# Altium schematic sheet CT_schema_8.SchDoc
size 405 x 220 mm
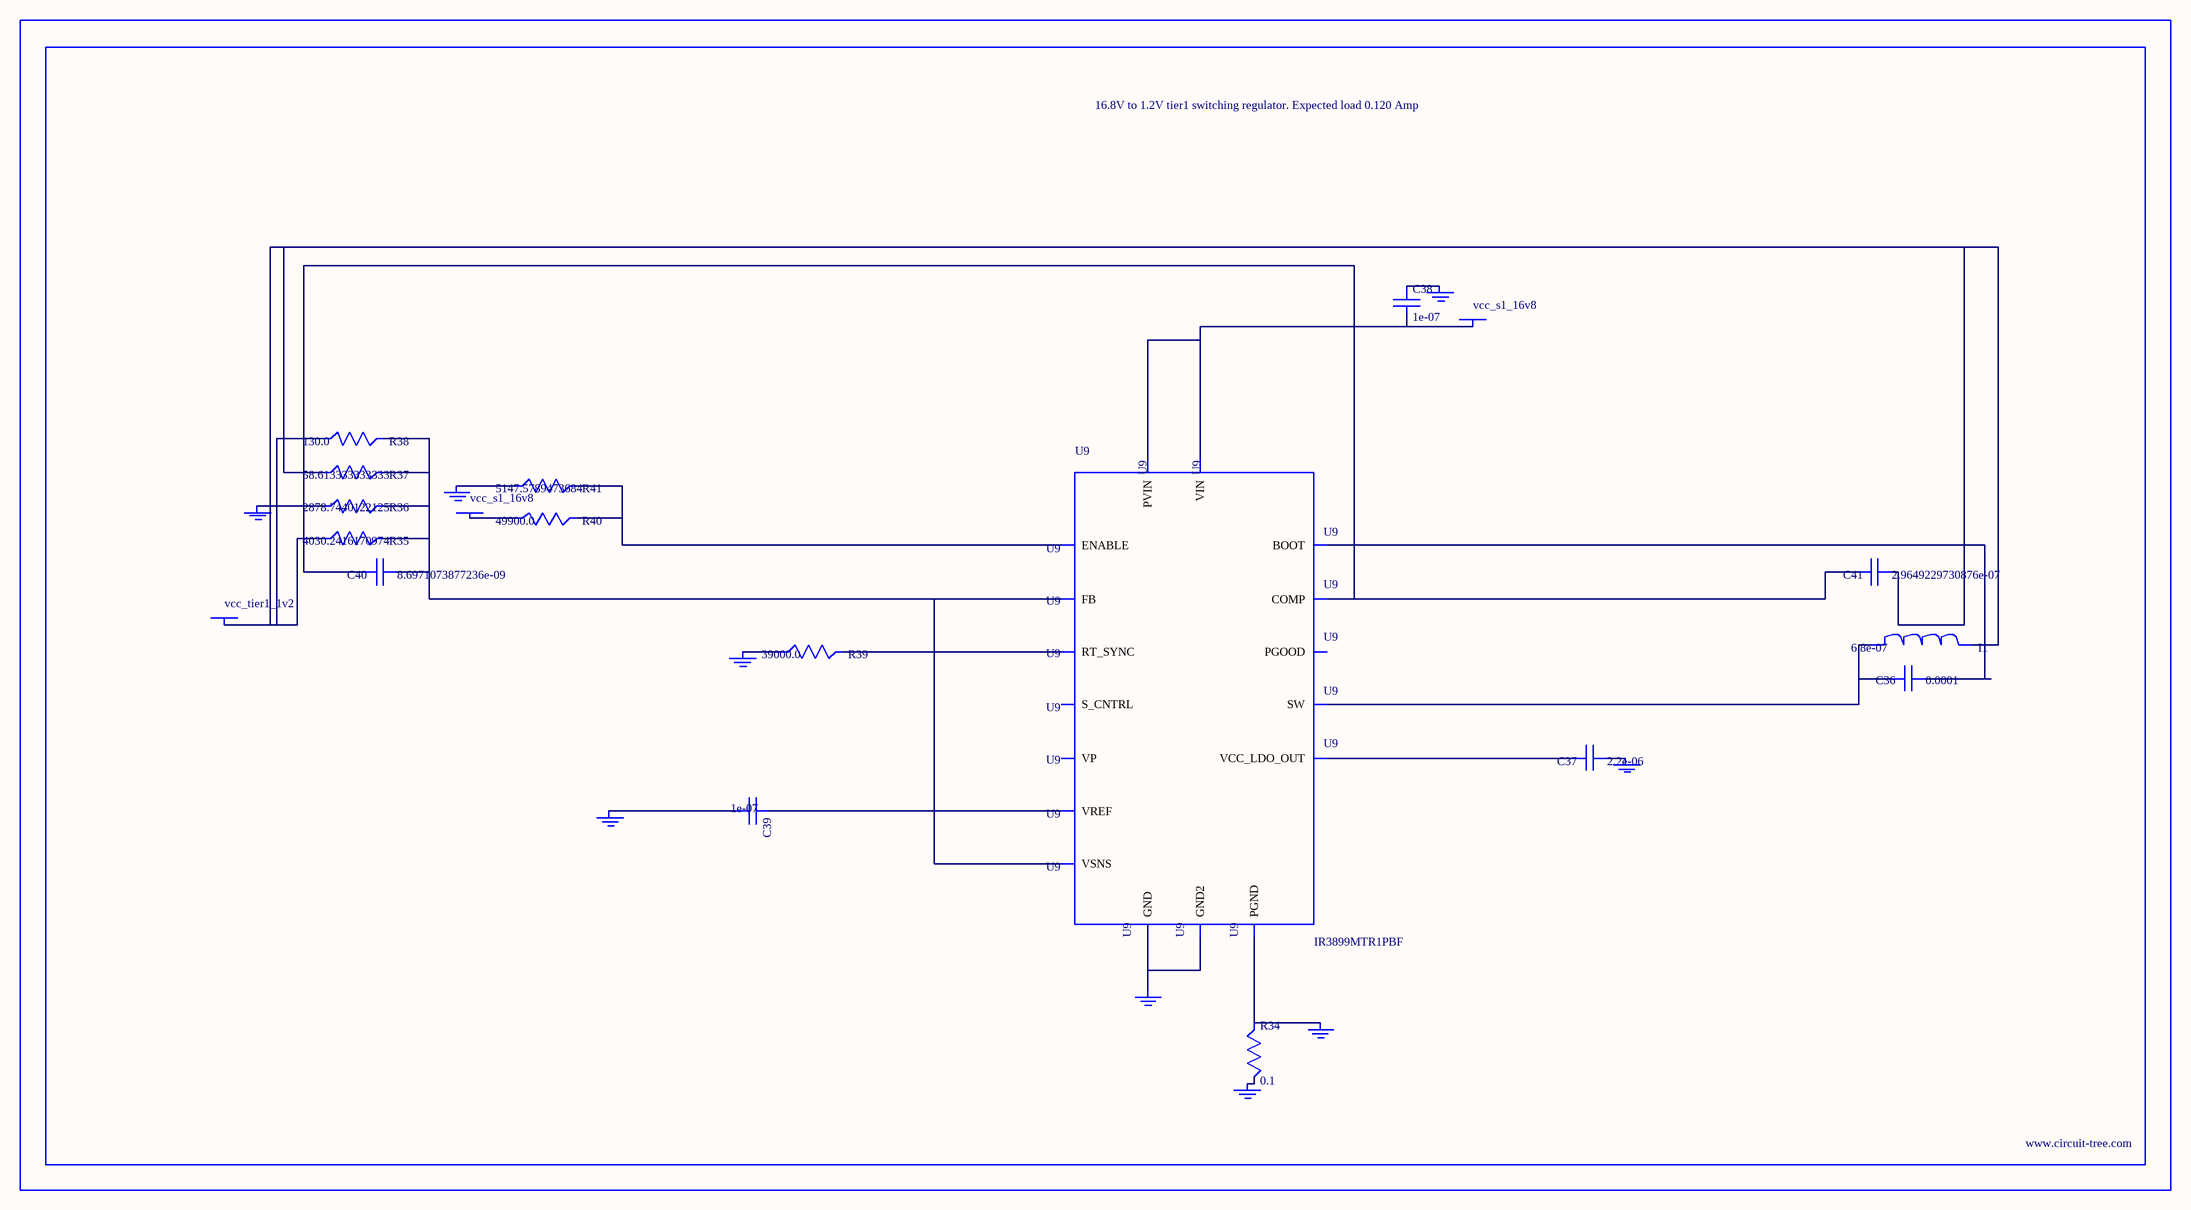
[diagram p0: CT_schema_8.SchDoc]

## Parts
BORDER7  (no value)
C36  0.0001  [C1210]
C37  2.2e-06  [C0603]
C38  1e-07  [C0402]
C39  1e-07  [C0402]
C40  8.6971073877236e-09  [R0603]
C41  2.9649229730876e-07  [R0603]
GND_INSTANCE_7_0  (no value)
GND_INSTANCE_7_1  (no value)
GND_INSTANCE_7_2  (no value)
GND_INSTANCE_7_3  (no value)
GND_INSTANCE_7_4  (no value)
GND_INSTANCE_7_5  (no value)
GND_INSTANCE_7_6  (no value)
GND_INSTANCE_7_7  (no value)
GND_INSTANCE_7_8  (no value)
I1  6.8e-07  [IND25X25CZ]
POWER_INSTANCE_7_0  vcc_s1_16v8
POWER_INSTANCE_7_1  vcc_s1_16v8
POWER_INSTANCE_7_2  vcc_tier1_1v2
R34  0.1  [R0603]
R35  4030.2416170974  [R0603]
R36  2878.7440122125  [R0603]
R37  58.613333333333  [R0603]
R38  130.0  [R0603]
R39  39000.0  [R0603]
R40  49900.0  [R0603]
R41  5147.5789473684  [R0603]
U9  IR3899MTR1PBF  [IR3899MTR1PBF]

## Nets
NetC36_1: C36.1 U9.14(BOOT)
NetC36_2: C36.2 I1.1 U9.12(SW)
NetC37_1: C37.1 GND_INSTANCE_7_4.0(GND)
NetC37_2: C37.2 U9.10(VCC_LDO_OUT)
NetC38_1: C38.1 GND_INSTANCE_7_3.0(GND)
NetC38_2: C38.2 POWER_INSTANCE_7_0.0(PWR) U9.9(VIN) U9.13(PVIN)
NetC39_1: C39.1 U9.2(VREF)
NetC39_2: C39.2 GND_INSTANCE_7_1.0(GND)
NetC40_1: C40.1 R35.2 R36.2 R37.2 R38.2 U9.1(FB) U9.8(VSNS)
NetC40_2: C40.2 C41.2 U9.3(COMP)
NetC41_1: C41.1 I1.2 POWER_INSTANCE_7_2.0(PWR) R35.1 R37.1 R38.1
NetGND_INSTANCE_7_0_0: GND_INSTANCE_7_0.0(GND) R36.1
NetGND_INSTANCE_7_2_0: GND_INSTANCE_7_2.0(GND) R39.1
NetGND_INSTANCE_7_5_0: GND_INSTANCE_7_5.0(GND) R34.2
NetGND_INSTANCE_7_6_0: GND_INSTANCE_7_6.0(GND) R34.1 U9.11(PGND)
NetGND_INSTANCE_7_7_0: GND_INSTANCE_7_7.0(GND) R41.1
NetGND_INSTANCE_7_8_0: GND_INSTANCE_7_8.0(GND) U9.4(GND) U9.17(GND2)
NetPOWER_INSTANCE_7_1_0: POWER_INSTANCE_7_1.0(PWR) R40.1
NetR39_2: R39.2 U9.5(RT_SYNC)
NetR40_2: R40.2 R41.2 U9.15(ENABLE)

Not connected (* = marked no-connect by the designer): U9 6(S_CNTRL) 7(PGOOD) 16(VP)

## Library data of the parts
BORDER7 = BORDER_PAGE7
C36 = GRM32ER61A107ME20L
C37 = C0603C225K8RACTU
C38 C39 = C0402C104K3RACTU
C40 = C40
C41 = C41
GND_INSTANCE_7_0-GND_INSTANCE_7_8 = GND
I1 = IHLP2525CZERR68M01
POWER_INSTANCE_7_0-POWER_INSTANCE_7_2 = PWR
R34 = ERJ-3RSFR10V
R35 = R35
R36 = R36
R37 = R37
R38 = RC0603JR-07130RL
R39 = RC0603JR-0739KL
R40 = RC0603FR-0749K9
R41 = R41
